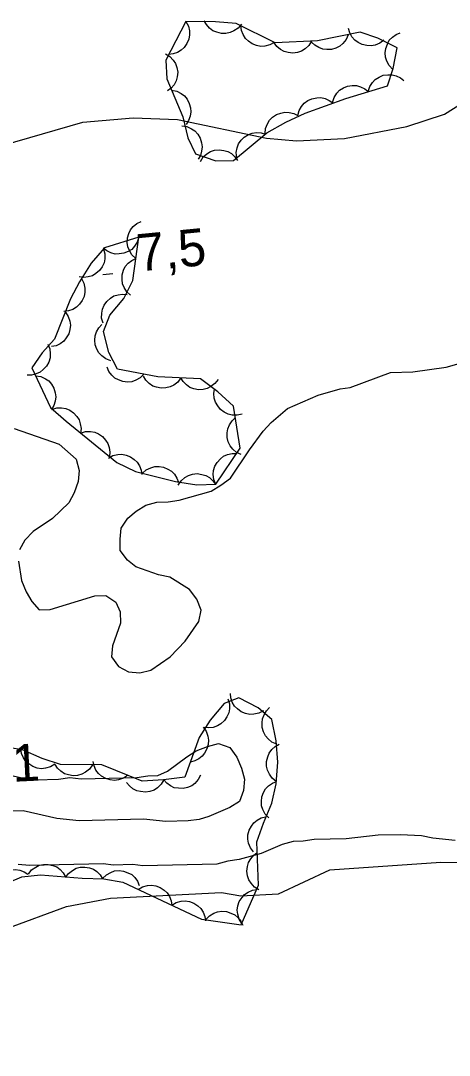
# Model space of a CAD drawing. Extents: x 336540 to 340074, y 5572036 to 5573747.
# Drawn here: x 337154.8 to 337189.3, y 5573142.9 to 5573226.2 of the extents above; entities that cross this region are included whole.
import ezdxf

# ---------------------------------------------------------------- set-up
doc = ezdxf.new("R2010")
doc.units = 0
for name, color, linetype in [('Niveau 2', 7, 'Continuous'), ('Niveau 3', 7, 'Continuous'), ('Niveau 44', 7, 'Continuous')]:
    doc.layers.add(name, color=color, linetype=linetype)

msp = doc.modelspace()

# ---------------------------------------------------------------- linework, layer by layer
at = {"layer": 'Niveau 2'}
for points in [[(337153.27, 5573216.18), (337159.76, 5573218.05), (337163.81, 5573218.41), (337167.37, 5573218.28), (337174.55, 5573216.77), (337176.96, 5573216.56), (337180.83, 5573216.75), (337185.85, 5573217.7), (337188.86, 5573218.69), (337190.33, 5573219.62)], [(337154.57, 5573182.69), (337154.83, 5573181.12), (337155.19, 5573180.22), (337155.66, 5573179.45), (337156.23, 5573178.78), (337157.13, 5573178.8), (337160.71, 5573179.9), (337161.61, 5573179.92), (337162.41, 5573179.38), (337162.77, 5573178.6), (337162.79, 5573177.7), (337162.15, 5573175.88), (337162.06, 5573174.98), (337162.64, 5573174.2), (337163.44, 5573173.77), (337164.34, 5573173.68), (337165.23, 5573173.92), (337166.79, 5573174.97), (337168, 5573176.24), (337169.09, 5573177.84), (337169.29, 5573178.74), (337168.93, 5573179.64), (337168.35, 5573180.41), (337166.76, 5573181.39), (337165.85, 5573181.59), (337164.03, 5573182.23), (337163.35, 5573182.77), (337162.77, 5573183.55), (337162.75, 5573184.45), (337162.84, 5573185.35), (337163.38, 5573186.15), (337164.05, 5573186.73), (337164.82, 5573187.2), (337165.72, 5573187.44), (337166.62, 5573187.46), (337167.52, 5573187.6), (337170.09, 5573188.33), (337170.87, 5573188.8), (337171.64, 5573189.38), (337173.16, 5573191.67), (337174.26, 5573193.16), (337174.92, 5573193.85), (337176.24, 5573195), (337178.69, 5573196.07), (337180.48, 5573196.56), (337181.27, 5573196.69), (337184.51, 5573197.89), (337186.31, 5573197.93), (337189, 5573198.33), (337190.79, 5573198.82)], [(337154.22, 5573193.37), (337157.85, 5573192.11), (337159.22, 5573190.9), (337159.47, 5573190), (337159.38, 5573189.1), (337159.06, 5573188.19), (337158.63, 5573187.39), (337157.31, 5573186.13), (337155.75, 5573185.08), (337155.09, 5573184.39), (337154.66, 5573183.59)], [(337153.3, 5573165.58), (337155.11, 5573165.17), (337156.01, 5573165.08), (337157.81, 5573165.12), (337158.71, 5573165.25), (337159.61, 5573165.16), (337164.1, 5573165.26), (337165, 5573165.4), (337165.79, 5573165.42), (337166.57, 5573165.77), (337168.12, 5573166.93), (337168.89, 5573167.4), (337169.78, 5573167.76), (337170.68, 5573168), (337171.59, 5573167.68), (337172.16, 5573166.91), (337172.52, 5573166.02), (337172.77, 5573165.12), (337172.68, 5573164.22), (337172.36, 5573163.32), (337171.58, 5573162.85), (337169.91, 5573162.13), (337169.13, 5573161.89), (337168.23, 5573161.76), (337166.43, 5573161.72), (337164.63, 5573161.9), (337159.46, 5573161.78), (337157.66, 5573161.97), (337154.94, 5573162.58), (337154.04, 5573162.56)], [(337189.74, 5573160.19), (337187.94, 5573160.37), (337187.03, 5573160.57), (337185.34, 5573160.65), (337183.54, 5573160.61), (337180.96, 5573160.32), (337178.37, 5573160.26), (337177.48, 5573160.13), (337176.69, 5573160.11), (337175.79, 5573159.87), (337174.12, 5573159.15), (337172.33, 5573158.66), (337171.43, 5573158.53), (337170.54, 5573158.28), (337164.58, 5573158.15), (337163.79, 5573158.24), (337162.21, 5573158.21), (337161.42, 5573158.3), (337155.46, 5573158.17), (337154.56, 5573158.26)], [(337082.56, 5573143.32), (337087.48, 5573142.88), (337092.04, 5573143.3), (337096.7, 5573144.54), (337102.5, 5573147.06), (337108.09, 5573150.24), (337116.69, 5573154.24), (337119.84, 5573155.41), (337130.44, 5573156.82), (337132.98, 5573156.95), (337138.92, 5573156.39), (337143.71, 5573155.29), (337147.18, 5573153.44), (337148.91, 5573152.66), (337150.79, 5573152.6), (337153.65, 5573153.09), (337158.45, 5573154.86), (337161.99, 5573155.55), (337170.93, 5573156), (337172.47, 5573155.74), (337175.51, 5573155.9), (337179.64, 5573157.82), (337188.57, 5573158.43), (337198.57, 5573158.28)]]:
    msp.add_lwpolyline(points, dxfattribs=at)
at = {"layer": 'Niveau 3'}
msp.add_line((337161.37, 5573205.78), (337162.17, 5573205.86), dxfattribs=at)
at = {"layer": 'Niveau 44'}
for points in [[(337168.05, 5573226.17), (337166.43, 5573223.04), (337166.52, 5573221.54), (337167.81, 5573218.49), (337168.2, 5573216.78), (337168.82, 5573215.51), (337170.47, 5573214.93), (337171.88, 5573214.97), (337174.56, 5573217.2), (337176.09, 5573218.05), (337177.64, 5573218.79), (337180.92, 5573219.97), (337184.27, 5573220.99), (337184.73, 5573222.39), (337185.06, 5573224.04), (337183.51, 5573224.83), (337182.07, 5573225.3), (337178.64, 5573224.6), (337175.24, 5573224.45), (337172.09, 5573226), (337170.43, 5573226.15), (337168.05, 5573226.17)], [(337168.05, 5573226.17), (337168.25, 5573225.8), (337168.33, 5573225.4), (337168.35, 5573225.08), (337168.28, 5573224.73), (337168.14, 5573224.39), (337167.91, 5573224.08), (337167.68, 5573223.85), (337167.38, 5573223.67), (337167.03, 5573223.55), (337166.67, 5573223.51)], [(337172.52, 5573225.96), (337172.26, 5573225.64), (337171.92, 5573225.41), (337171.62, 5573225.27), (337171.28, 5573225.21), (337170.91, 5573225.21), (337170.54, 5573225.31), (337170.23, 5573225.42), (337169.96, 5573225.64), (337169.71, 5573225.92), (337169.53, 5573226.23)], [(337175.17, 5573224.48), (337174.81, 5573224.28), (337174.41, 5573224.19), (337174.08, 5573224.16), (337173.74, 5573224.23), (337173.39, 5573224.36), (337173.08, 5573224.58), (337172.84, 5573224.8), (337172.66, 5573225.11), (337172.53, 5573225.45), (337172.48, 5573225.81)], [(337183.99, 5573224.67), (337183.66, 5573224.42), (337183.28, 5573224.27), (337182.96, 5573224.2), (337182.61, 5573224.22), (337182.25, 5573224.3), (337181.91, 5573224.48), (337181.64, 5573224.66), (337181.42, 5573224.93), (337181.24, 5573225.26), (337181.14, 5573225.6)], [(337178.16, 5573224.58), (337177.94, 5573224.22), (337177.64, 5573223.95), (337177.36, 5573223.77), (337177.03, 5573223.66), (337176.66, 5573223.62), (337176.28, 5573223.66), (337175.96, 5573223.74), (337175.66, 5573223.92), (337175.38, 5573224.16), (337175.16, 5573224.45)], [(337181.11, 5573225.1), (337180.95, 5573224.72), (337180.69, 5573224.4), (337180.45, 5573224.18), (337180.13, 5573224.02), (337179.78, 5573223.92), (337179.4, 5573223.9), (337179.07, 5573223.93), (337178.74, 5573224.06), (337178.43, 5573224.25), (337178.17, 5573224.5)], [(337184.71, 5573222.31), (337184.42, 5573222.61), (337184.23, 5573222.97), (337184.12, 5573223.28), (337184.1, 5573223.63), (337184.14, 5573224), (337184.27, 5573224.35), (337184.42, 5573224.65), (337184.67, 5573224.9), (337184.97, 5573225.11), (337185.3, 5573225.25)], [(337166.4, 5573223.56), (337166.76, 5573223.35), (337167.03, 5573223.05), (337167.22, 5573222.78), (337167.33, 5573222.45), (337167.39, 5573222.08), (337167.34, 5573221.7), (337167.27, 5573221.38), (337167.1, 5573221.07), (337166.86, 5573220.79), (337166.58, 5573220.57)], [(337182.73, 5573220.52), (337182.86, 5573220.92), (337183.08, 5573221.26), (337183.3, 5573221.5), (337183.6, 5573221.69), (337183.94, 5573221.83), (337184.32, 5573221.88), (337184.65, 5573221.88), (337184.99, 5573221.78), (337185.32, 5573221.62), (337185.6, 5573221.4)], [(337166.9, 5573220.64), (337167.31, 5573220.56), (337167.67, 5573220.37), (337167.94, 5573220.18), (337168.15, 5573219.9), (337168.32, 5573219.57), (337168.41, 5573219.2), (337168.45, 5573218.88), (337168.39, 5573218.53), (337168.26, 5573218.18), (337168.07, 5573217.88)], [(337179.86, 5573219.65), (337179.99, 5573220.05), (337180.21, 5573220.38), (337180.43, 5573220.63), (337180.73, 5573220.82), (337181.07, 5573220.95), (337181.45, 5573221), (337181.78, 5573221.01), (337182.12, 5573220.91), (337182.45, 5573220.75), (337182.73, 5573220.52)], [(337177.06, 5573218.58), (337177.16, 5573218.99), (337177.37, 5573219.33), (337177.58, 5573219.59), (337177.87, 5573219.79), (337178.2, 5573219.94), (337178.58, 5573220.01), (337178.91, 5573220.04), (337179.25, 5573219.95), (337179.59, 5573219.81), (337179.88, 5573219.6)], [(337174.43, 5573217.13), (337174.46, 5573217.54), (337174.62, 5573217.92), (337174.78, 5573218.21), (337175.03, 5573218.45), (337175.34, 5573218.66), (337175.7, 5573218.79), (337176.02, 5573218.86), (337176.37, 5573218.83), (337176.73, 5573218.75), (337177.05, 5573218.58)], [(337167.72, 5573217.76), (337168.13, 5573217.7), (337168.5, 5573217.53), (337168.78, 5573217.35), (337169.01, 5573217.09), (337169.2, 5573216.77), (337169.31, 5573216.4), (337169.37, 5573216.08), (337169.32, 5573215.73), (337169.22, 5573215.38), (337169.04, 5573215.07)], [(337172.14, 5573215.18), (337172.1, 5573215.6), (337172.17, 5573216), (337172.28, 5573216.31), (337172.49, 5573216.6), (337172.75, 5573216.86), (337173.08, 5573217.05), (337173.38, 5573217.18), (337173.73, 5573217.22), (337174.1, 5573217.2), (337174.44, 5573217.1)], [(337169.22, 5573214.89), (337169.44, 5573215.25), (337169.75, 5573215.51), (337170.03, 5573215.69), (337170.36, 5573215.79), (337170.73, 5573215.83), (337171.11, 5573215.78), (337171.43, 5573215.7), (337171.73, 5573215.52), (337172, 5573215.27), (337172.21, 5573214.98)], [(337164.02, 5573207.08), (337163.71, 5573207.36), (337163.5, 5573207.71), (337163.37, 5573208.01), (337163.33, 5573208.36), (337163.35, 5573208.73), (337163.46, 5573209.09), (337163.59, 5573209.39), (337163.82, 5573209.66), (337164.11, 5573209.89), (337164.44, 5573210.05)], [(337164.26, 5573208.8), (337161.5, 5573207.94), (337160.43, 5573206.7), (337159.5, 5573205.2), (337158.77, 5573203.82), (337157.48, 5573200.56), (337156.47, 5573199.48), (337155.66, 5573198.26), (337157.16, 5573195.08), (337158.41, 5573193.96), (337162.48, 5573190.65), (337163.99, 5573189.91), (337167.21, 5573189.1), (337168.94, 5573188.84), (337170.45, 5573188.88), (337172.42, 5573191.79), (337171.88, 5573195.18), (337170.62, 5573196.32), (337169.24, 5573197.39), (337165.79, 5573197.53), (337162.54, 5573198.15), (337161.84, 5573199.49), (337161.42, 5573201.19), (337161.92, 5573202.5), (337163.05, 5573203.84), (337163.77, 5573205.31), (337164.26, 5573208.8)], [(337164.26, 5573208.8), (337164.14, 5573208.4), (337163.91, 5573208.06), (337163.7, 5573207.81), (337163.4, 5573207.63), (337163.06, 5573207.49), (337162.68, 5573207.44), (337162.35, 5573207.43), (337162.01, 5573207.52), (337161.68, 5573207.68), (337161.4, 5573207.91)], [(337161.43, 5573207.86), (337161.54, 5573207.45), (337161.53, 5573207.05), (337161.47, 5573206.72), (337161.32, 5573206.41), (337161.1, 5573206.11), (337160.81, 5573205.86), (337160.53, 5573205.68), (337160.19, 5573205.59), (337159.83, 5573205.54), (337159.47, 5573205.59)], [(337163.6, 5573204.11), (337163.29, 5573204.39), (337163.08, 5573204.74), (337162.95, 5573205.04), (337162.91, 5573205.39), (337162.93, 5573205.76), (337163.04, 5573206.12), (337163.17, 5573206.42), (337163.41, 5573206.69), (337163.7, 5573206.92), (337164.02, 5573207.08)], [(337159.64, 5573205.46), (337159.83, 5573205.09), (337159.91, 5573204.69), (337159.93, 5573204.36), (337159.85, 5573204.02), (337159.71, 5573203.68), (337159.48, 5573203.38), (337159.25, 5573203.14), (337158.94, 5573202.97), (337158.59, 5573202.85), (337158.23, 5573202.81)], [(337161.39, 5573201.87), (337161.27, 5573202.27), (337161.28, 5573202.68), (337161.33, 5573203), (337161.48, 5573203.32), (337161.7, 5573203.62), (337161.99, 5573203.87), (337162.26, 5573204.06), (337162.6, 5573204.15), (337162.96, 5573204.2), (337163.32, 5573204.16)], [(337158.35, 5573202.76), (337158.58, 5573202.41), (337158.71, 5573202.02), (337158.76, 5573201.7), (337158.72, 5573201.35), (337158.62, 5573200.99), (337158.42, 5573200.67), (337158.22, 5573200.41), (337157.93, 5573200.2), (337157.6, 5573200.04), (337157.24, 5573199.97)], [(337162, 5573198.84), (337161.61, 5573198.98), (337161.28, 5573199.23), (337161.05, 5573199.46), (337160.88, 5573199.77), (337160.76, 5573200.12), (337160.73, 5573200.5), (337160.74, 5573200.83), (337160.86, 5573201.16), (337161.04, 5573201.48), (337161.28, 5573201.75)], [(337156.93, 5573200.18), (337157.09, 5573199.79), (337157.13, 5573199.39), (337157.12, 5573199.06), (337157.01, 5573198.73), (337156.83, 5573198.4), (337156.57, 5573198.12), (337156.32, 5573197.91), (337156, 5573197.77), (337155.63, 5573197.68), (337155.27, 5573197.68)], [(337164.66, 5573197.75), (337164.37, 5573197.45), (337164.01, 5573197.26), (337163.7, 5573197.14), (337163.35, 5573197.12), (337162.98, 5573197.15), (337162.62, 5573197.29), (337162.33, 5573197.43), (337162.08, 5573197.68), (337161.86, 5573197.98), (337161.71, 5573198.31)], [(337155.96, 5573197.63), (337156.37, 5573197.57), (337156.74, 5573197.39), (337157.01, 5573197.21), (337157.24, 5573196.94), (337157.42, 5573196.62), (337157.53, 5573196.25), (337157.58, 5573195.93), (337157.53, 5573195.58), (337157.42, 5573195.23), (337157.24, 5573194.92)], [(337167.64, 5573197.45), (337167.39, 5573197.12), (337167.07, 5573196.88), (337166.78, 5573196.72), (337166.43, 5573196.64), (337166.06, 5573196.62), (337165.69, 5573196.7), (337165.38, 5573196.8), (337165.09, 5573197.01), (337164.83, 5573197.27), (337164.64, 5573197.58)], [(337170.64, 5573197.33), (337170.39, 5573197), (337170.06, 5573196.75), (337169.77, 5573196.59), (337169.43, 5573196.52), (337169.06, 5573196.5), (337168.69, 5573196.58), (337168.38, 5573196.68), (337168.09, 5573196.89), (337167.83, 5573197.15), (337167.64, 5573197.45)], [(337172.59, 5573194.54), (337172.18, 5573194.44), (337171.77, 5573194.46), (337171.45, 5573194.52), (337171.14, 5573194.69), (337170.84, 5573194.91), (337170.61, 5573195.21), (337170.43, 5573195.49), (337170.34, 5573195.83), (337170.31, 5573196.2), (337170.36, 5573196.55)], [(337157.25, 5573194.91), (337157.65, 5573195.03), (337158.05, 5573195.03), (337158.38, 5573194.98), (337158.7, 5573194.84), (337159.01, 5573194.63), (337159.26, 5573194.34), (337159.45, 5573194.07), (337159.55, 5573193.74), (337159.61, 5573193.37), (337159.58, 5573193.01)], [(337172.5, 5573191.28), (337172.12, 5573191.45), (337171.82, 5573191.72), (337171.61, 5573191.98), (337171.46, 5573192.3), (337171.37, 5573192.66), (337171.38, 5573193.04), (337171.42, 5573193.36), (337171.56, 5573193.68), (337171.77, 5573193.99), (337172.03, 5573194.24)], [(337159.58, 5573193.01), (337159.97, 5573193.13), (337160.38, 5573193.13), (337160.71, 5573193.09), (337161.03, 5573192.94), (337161.34, 5573192.74), (337161.59, 5573192.45), (337161.78, 5573192.18), (337161.88, 5573191.85), (337161.93, 5573191.48), (337161.9, 5573191.12)], [(337161.81, 5573190.98), (337162.17, 5573191.19), (337162.57, 5573191.28), (337162.9, 5573191.31), (337163.24, 5573191.24), (337163.59, 5573191.1), (337163.9, 5573190.88), (337164.14, 5573190.66), (337164.32, 5573190.36), (337164.46, 5573190.01), (337164.51, 5573189.66)], [(337170.45, 5573188.87), (337170.29, 5573189.26), (337170.26, 5573189.67), (337170.27, 5573190), (337170.39, 5573190.33), (337170.57, 5573190.65), (337170.83, 5573190.93), (337171.08, 5573191.14), (337171.41, 5573191.28), (337171.77, 5573191.36), (337172.13, 5573191.36)], [(337164.55, 5573189.77), (337164.86, 5573190.05), (337165.23, 5573190.22), (337165.54, 5573190.32), (337165.89, 5573190.32), (337166.26, 5573190.26), (337166.61, 5573190.11), (337166.89, 5573189.95), (337167.13, 5573189.69), (337167.33, 5573189.38), (337167.46, 5573189.04)], [(337167.44, 5573188.8), (337167.67, 5573189.15), (337167.98, 5573189.42), (337168.26, 5573189.6), (337168.59, 5573189.7), (337168.96, 5573189.74), (337169.34, 5573189.68), (337169.66, 5573189.6), (337169.96, 5573189.42), (337170.23, 5573189.17), (337170.44, 5573188.88)], [(337174.29, 5573170.64), (337173.92, 5573170.44), (337173.52, 5573170.36), (337173.19, 5573170.34), (337172.85, 5573170.42), (337172.51, 5573170.56), (337172.2, 5573170.79), (337171.96, 5573171.02), (337171.79, 5573171.32), (337171.67, 5573171.67), (337171.63, 5573172.03)], [(337151.79, 5573155.98), (337154.84, 5573157.26), (337156.36, 5573157.41), (337159.69, 5573157.16), (337161.44, 5573157.11), (337162.98, 5573156.82), (337169.31, 5573153.86), (337172.5, 5573153.38), (337173.91, 5573156.58), (337173.77, 5573160.08), (337174.29, 5573161.59), (337174.98, 5573163.2), (337175.31, 5573164.75), (337175.44, 5573166.5), (337175.31, 5573168.22), (337174.98, 5573169.93), (337173.87, 5573170.86), (337172.32, 5573171.67), (337171.13, 5573171.22), (337170.01, 5573169.87), (337169.13, 5573168.49), (337167.98, 5573165.3), (337166.24, 5573165.08), (337164.54, 5573164.96), (337161.28, 5573166.27), (337157.96, 5573166.31), (337156.49, 5573166.79), (337154.89, 5573167.49), (337153.2, 5573167.77)], [(337171.44, 5573171.6), (337171.56, 5573171.2), (337171.56, 5573170.79), (337171.51, 5573170.46), (337171.36, 5573170.14), (337171.15, 5573169.84), (337170.86, 5573169.59), (337170.59, 5573169.41), (337170.25, 5573169.3), (337169.89, 5573169.25), (337169.53, 5573169.29)], [(337175.36, 5573167.94), (337174.98, 5573168.11), (337174.67, 5573168.37), (337174.45, 5573168.61), (337174.29, 5573168.93), (337174.19, 5573169.29), (337174.18, 5573169.67), (337174.21, 5573169.99), (337174.34, 5573170.32), (337174.54, 5573170.63), (337174.79, 5573170.89)], [(337169.43, 5573169.32), (337169.68, 5573168.98), (337169.81, 5573168.6), (337169.88, 5573168.28), (337169.84, 5573167.92), (337169.75, 5573167.57), (337169.56, 5573167.23), (337169.37, 5573166.97), (337169.09, 5573166.76), (337168.76, 5573166.59), (337168.41, 5573166.5)], [(337175.32, 5573164.95), (337175, 5573165.21), (337174.77, 5573165.54), (337174.61, 5573165.84), (337174.55, 5573166.18), (337174.55, 5573166.55), (337174.64, 5573166.92), (337174.75, 5573167.23), (337174.96, 5573167.51), (337175.23, 5573167.76), (337175.55, 5573167.94)], [(337157.51, 5573166.34), (337157.16, 5573166.12), (337156.76, 5573166.01), (337156.44, 5573165.97), (337156.09, 5573166.02), (337155.74, 5573166.14), (337155.42, 5573166.35), (337155.17, 5573166.56), (337154.97, 5573166.85), (337154.83, 5573167.19), (337154.76, 5573167.55)], [(337160.53, 5573166.28), (337160.29, 5573165.94), (337159.97, 5573165.68), (337159.68, 5573165.52), (337159.34, 5573165.43), (337158.97, 5573165.4), (337158.6, 5573165.47), (337158.28, 5573165.56), (337157.99, 5573165.76), (337157.72, 5573166.01), (337157.53, 5573166.32)], [(337163.36, 5573165.43), (337163.02, 5573165.2), (337162.63, 5573165.08), (337162.3, 5573165.02), (337161.95, 5573165.07), (337161.6, 5573165.18), (337161.27, 5573165.38), (337161.01, 5573165.57), (337160.81, 5573165.86), (337160.66, 5573166.2), (337160.58, 5573166.55)], [(337169.24, 5573165.46), (337169.05, 5573165.09), (337168.77, 5573164.79), (337168.52, 5573164.59), (337168.19, 5573164.46), (337167.83, 5573164.38), (337167.45, 5573164.39), (337167.12, 5573164.44), (337166.81, 5573164.6), (337166.51, 5573164.81), (337166.27, 5573165.08)], [(337166.27, 5573165.08), (337166.06, 5573164.72), (337165.76, 5573164.44), (337165.49, 5573164.25), (337165.16, 5573164.14), (337164.79, 5573164.08), (337164.41, 5573164.12), (337164.09, 5573164.18), (337163.79, 5573164.36), (337163.5, 5573164.59), (337163.27, 5573164.87)], [(337174.73, 5573162.01), (337174.44, 5573162.31), (337174.25, 5573162.67), (337174.14, 5573162.98), (337174.13, 5573163.34), (337174.17, 5573163.7), (337174.31, 5573164.06), (337174.46, 5573164.35), (337174.71, 5573164.6), (337175.02, 5573164.81), (337175.35, 5573164.94)], [(337173.49, 5573159.26), (337173.24, 5573159.59), (337173.1, 5573159.98), (337173.03, 5573160.3), (337173.05, 5573160.65), (337173.14, 5573161.01), (337173.33, 5573161.34), (337173.51, 5573161.61), (337173.79, 5573161.83), (337174.12, 5573162), (337174.46, 5573162.1)], [(337173.92, 5573156.21), (337173.57, 5573156.43), (337173.3, 5573156.74), (337173.12, 5573157.02), (337173.01, 5573157.35), (337172.97, 5573157.72), (337173.02, 5573158.1), (337173.09, 5573158.42), (337173.27, 5573158.72), (337173.52, 5573159), (337173.8, 5573159.21)], [(337152.56, 5573156.3), (337152.64, 5573156.71), (337152.84, 5573157.07), (337153.03, 5573157.34), (337153.31, 5573157.55), (337153.64, 5573157.73), (337154.01, 5573157.81), (337154.33, 5573157.85), (337154.68, 5573157.79), (337155.03, 5573157.66), (337155.33, 5573157.47)], [(337155.37, 5573157.48), (337155.62, 5573157.81), (337155.96, 5573158.04), (337156.25, 5573158.19), (337156.6, 5573158.26), (337156.97, 5573158.26), (337157.34, 5573158.17), (337157.65, 5573158.06), (337157.93, 5573157.84), (337158.18, 5573157.57), (337158.36, 5573157.26)], [(337158.35, 5573157.2), (337158.6, 5573157.54), (337158.92, 5573157.78), (337159.21, 5573157.95), (337159.55, 5573158.03), (337159.92, 5573158.05), (337160.29, 5573157.98), (337160.61, 5573157.88), (337160.89, 5573157.68), (337161.16, 5573157.42), (337161.35, 5573157.11)], [(337161.35, 5573157.13), (337161.65, 5573157.42), (337162.01, 5573157.62), (337162.31, 5573157.73), (337162.67, 5573157.76), (337163.03, 5573157.72), (337163.39, 5573157.59), (337163.69, 5573157.44), (337163.94, 5573157.2), (337164.16, 5573156.9), (337164.3, 5573156.57)], [(337164.2, 5573156.25), (337164.56, 5573156.46), (337164.95, 5573156.56), (337165.28, 5573156.6), (337165.63, 5573156.54), (337165.97, 5573156.41), (337166.29, 5573156.19), (337166.54, 5573155.98), (337166.72, 5573155.68), (337166.86, 5573155.33), (337166.92, 5573154.98)], [(337172.55, 5573153.5), (337172.33, 5573153.85), (337172.22, 5573154.25), (337172.18, 5573154.57), (337172.23, 5573154.92), (337172.35, 5573155.27), (337172.57, 5573155.59), (337172.77, 5573155.84), (337173.07, 5573156.03), (337173.41, 5573156.18), (337173.76, 5573156.25)], [(337166.92, 5573154.98), (337167.27, 5573155.19), (337167.67, 5573155.29), (337168, 5573155.33), (337168.34, 5573155.27), (337168.69, 5573155.14), (337169.01, 5573154.92), (337169.25, 5573154.71), (337169.44, 5573154.41), (337169.58, 5573154.06), (337169.63, 5573153.71)], [(337169.66, 5573153.81), (337169.95, 5573154.11), (337170.3, 5573154.32), (337170.6, 5573154.45), (337170.95, 5573154.49), (337171.32, 5573154.46), (337171.68, 5573154.34), (337171.98, 5573154.21), (337172.24, 5573153.97), (337172.47, 5573153.69), (337172.63, 5573153.36)]]:
    msp.add_lwpolyline(points, dxfattribs=at)

# ---------------------------------------------------------------- texts
at = {"layer": 'Niveau 3'}
for s, rotation, p in [('7,5    ', 5.5424, (337164.24, 5573206.02)), ('9,1    ', 2.7712, (337150.79, 5573164.75))]:
    msp.add_text(s, height=3, rotation=rotation, dxfattribs=at).set_placement(p)

doc.saveas('drawing.dxf')
